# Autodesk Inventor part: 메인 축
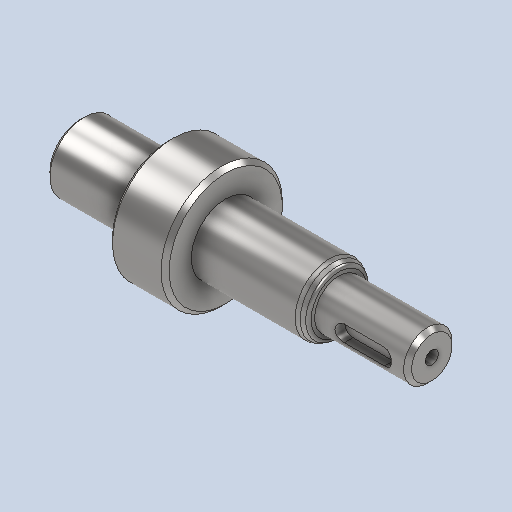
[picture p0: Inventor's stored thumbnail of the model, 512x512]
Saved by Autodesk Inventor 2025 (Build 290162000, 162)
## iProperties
Created: 2024-07
Part Number: 메인 축
Material: 강철, 연강
Document SubType Name: Modeling
Designer: SAMSUNG
Density: 7.86 g/cm^3
Appearance: 기본값
Author: jhkim
Revision Number: 1
Sending System: Autodesk Inventor 2025
Preprocessor: ST-DEVELOPER v20
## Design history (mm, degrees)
feature "솔리드1"
node "솔리드2"
